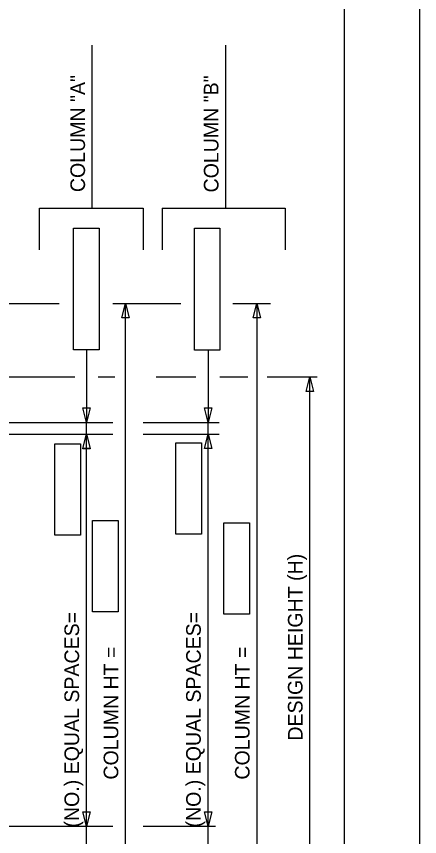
# Model space of a CAD drawing. Extents: x 3831399 to 3833095, y 499014 to 500202.
# Drawn here: x 3833000.9 to 3833081.2, y 499832.5 to 499995.8 of the extents above; entities that cross this region are included whole.
import ezdxf

# ---------------------------------------------------------------- set-up
doc = ezdxf.new("R2010")
doc.units = 0
for name, color, linetype in [('2', 7, 'Continuous'), ('Default', 7, 'Continuous'), ('DIM TXT', 7, 'Continuous'), ('PLT-BNDY', 7, 'Continuous')]:
    doc.layers.add(name, color=color, linetype=linetype)

msp = doc.modelspace()

# ---------------------------------------------------------------- linework, layer by layer
at = {"layer": '2'}
msp.add_line((3833066.16, 500187.03), (3833066.16, 499623.03), dxfattribs=at)
at = {"layer": 'Default'}
for p, q in [((3833005.52, 499949.31), (3833005.52, 499957.6)), ((3833005.52, 499957.6), (3833026.18, 499957.6)), ((3833026.18, 499957.6), (3833026.18, 499949.31)), ((3833029.92, 499957.6), (3833029.92, 499949.31)), ((3833029.92, 499957.6), (3833054.41, 499957.6)), ((3833054.41, 499957.6), (3833054.41, 499949.31)), ((3833012.3, 499929.41), (3833012.3, 499953.66)), ((3833012.3, 499953.66), (3833017.39, 499953.66)), ((3833017.39, 499953.66), (3833017.39, 499929.41)), ((3833036.36, 499929.38), (3833036.36, 499953.62)), ((3833036.36, 499953.62), (3833041.45, 499953.62)), ((3833041.45, 499953.62), (3833041.45, 499929.38)), ((3833017.39, 499929.41), (3833012.3, 499929.41)), ((3833041.45, 499929.38), (3833036.36, 499929.38)), ((3833008.6, 499892.55), (3833008.6, 499910.73)), ((3833008.6, 499910.73), (3833013.69, 499910.73)), ((3833013.69, 499910.73), (3833013.69, 499892.55)), ((3833032.65, 499892.76), (3833032.65, 499910.95)), ((3833032.65, 499910.95), (3833037.74, 499910.95)), ((3833037.74, 499910.95), (3833037.74, 499892.76)), ((3833016.12, 499877.27), (3833016.12, 499895.45)), ((3833016.12, 499895.45), (3833021.21, 499895.45)), ((3833021.21, 499895.45), (3833021.21, 499877.27)), ((3833042.23, 499876.84), (3833042.23, 499895.03)), ((3833042.23, 499895.03), (3833047.32, 499895.03)), ((3833047.32, 499895.03), (3833047.32, 499876.84)), ((3833013.69, 499892.55), (3833008.6, 499892.55)), ((3833037.74, 499892.76), (3833032.65, 499892.76)), ((3833021.21, 499877.27), (3833016.12, 499877.27)), ((3833047.32, 499876.84), (3833042.23, 499876.84))]:
    msp.add_line(p, q, dxfattribs=at)
at = {"layer": 'DIM TXT'}
for p, q in [((3833015.97, 499990.07), (3833015.97, 499957.6)), ((3833042.52, 499990.07), (3833042.52, 499957.6)), ((3832959.5, 499938.68), (3833009.43, 499938.68)), ((3833020.12, 499938.68), (3833033.68, 499938.68)), ((3833022.67, 499826.25), (3833022.67, 499938.68)), ((3833044, 499938.68), (3833051.5, 499938.68)), ((3833048.79, 499938.68), (3833048.79, 499826.25)), ((3833014.87, 499929.35), (3833014.87, 499914.97)), ((3833039.09, 499929.35), (3833039.09, 499914.95)), ((3832977.71, 499924.07), (3833012.57, 499924.07)), ((3833017.24, 499924.07), (3833020.56, 499924.07)), ((3833028.75, 499924.07), (3833036.64, 499924.07)), ((3833041.4, 499924.07), (3833046.96, 499924.07)), ((3833050.82, 499924.07), (3833060.79, 499924.07)), ((3833059.34, 499826.25), (3833059.34, 499924.07)), ((3832953.42, 499914.97), (3833020.11, 499914.97)), ((3833014.87, 499912.67), (3833014.87, 499914.97)), ((3833026.18, 499914.97), (3833041.27, 499914.97)), ((3833039.09, 499912.68), (3833039.09, 499914.95)), ((3832950.5, 499912.67), (3833020.11, 499912.67)), ((3833014.87, 499834.59), (3833014.87, 499912.68)), ((3833014.87, 499902.49), (3833014.87, 499912.67)), ((3833026.18, 499912.67), (3833041.27, 499912.67)), ((3833039.09, 499902.5), (3833039.09, 499912.68)), ((3833039.09, 499834.59), (3833039.09, 499912.68)), ((3833014.87, 499834.59), (3833014.87, 499840.41)), ((3833039.09, 499834.59), (3833039.09, 499840.41)), ((3832953.54, 499834.59), (3833020.11, 499834.59)), ((3833014.87, 499826.25), (3833014.87, 499834.59)), ((3833026.18, 499834.59), (3833040.54, 499834.59)), ((3833039.09, 499826.25), (3833039.09, 499834.59))]:
    msp.add_line(p, q, dxfattribs=at)
for points in [[(3833021.94, 499935.77), (3833022.67, 499938.68), (3833023.4, 499935.77)], [(3833048.07, 499935.77), (3833048.79, 499938.68), (3833049.52, 499935.77)], [(3833058.61, 499921.16), (3833059.34, 499924.07), (3833060.07, 499921.16)], [(3833015.6, 499917.88), (3833014.87, 499914.97), (3833014.14, 499917.88)], [(3833039.82, 499917.86), (3833039.09, 499914.95), (3833038.36, 499917.86)], [(3833014.14, 499909.77), (3833014.87, 499912.68), (3833015.6, 499909.77)], [(3833014.14, 499909.76), (3833014.87, 499912.67), (3833015.6, 499909.76)], [(3833038.36, 499909.77), (3833039.09, 499912.68), (3833039.82, 499909.77)], [(3833038.36, 499909.77), (3833039.09, 499912.68), (3833039.82, 499909.77)], [(3833015.6, 499837.5), (3833014.87, 499834.59), (3833014.14, 499837.5)], [(3833015.6, 499837.5), (3833014.87, 499834.59), (3833014.14, 499837.5)], [(3833039.82, 499837.5), (3833039.09, 499834.59), (3833038.36, 499837.5)], [(3833039.82, 499837.5), (3833039.09, 499834.59), (3833038.36, 499837.5)]]:
    msp.add_lwpolyline(points, close=True, dxfattribs=at)
at = {"layer": 'PLT-BNDY'}
msp.add_lwpolyline([(3832240.16, 500202.03), (3833081.16, 500202.03), (3833081.16, 499608.03), (3832240.16, 499608.03)], close=True, dxfattribs=at)

# ---------------------------------------------------------------- texts
at = {"layer": 'DIM TXT'}
for s, height, rotation, p in [('COLUMN "A"', 2.91, 90.0006, (3833014.6, 499960.83)), ('COLUMN "B"', 2.91, 90.0741, (3833041.16, 499960.76)), ('DESIGN HEIGHT (H)', 2.9099, 90, (3833057.88, 499851.65)), ('  (NO.) EQUAL SPACES=        ', 2.9099, 90, (3833013.42, 499832.18)), ('  (NO.) EQUAL SPACES=        ', 2.9099, 90, (3833037.63, 499832.19)), ('COLUMN HT =           ', 2.9099, 90, (3833021.22, 499843.89)), ('COLUMN HT =           ', 2.9099, 90, (3833047.34, 499843.89))]:
    msp.add_text(s, height=height, rotation=rotation, dxfattribs=at).set_placement(p)

doc.saveas('drawing.dxf')
